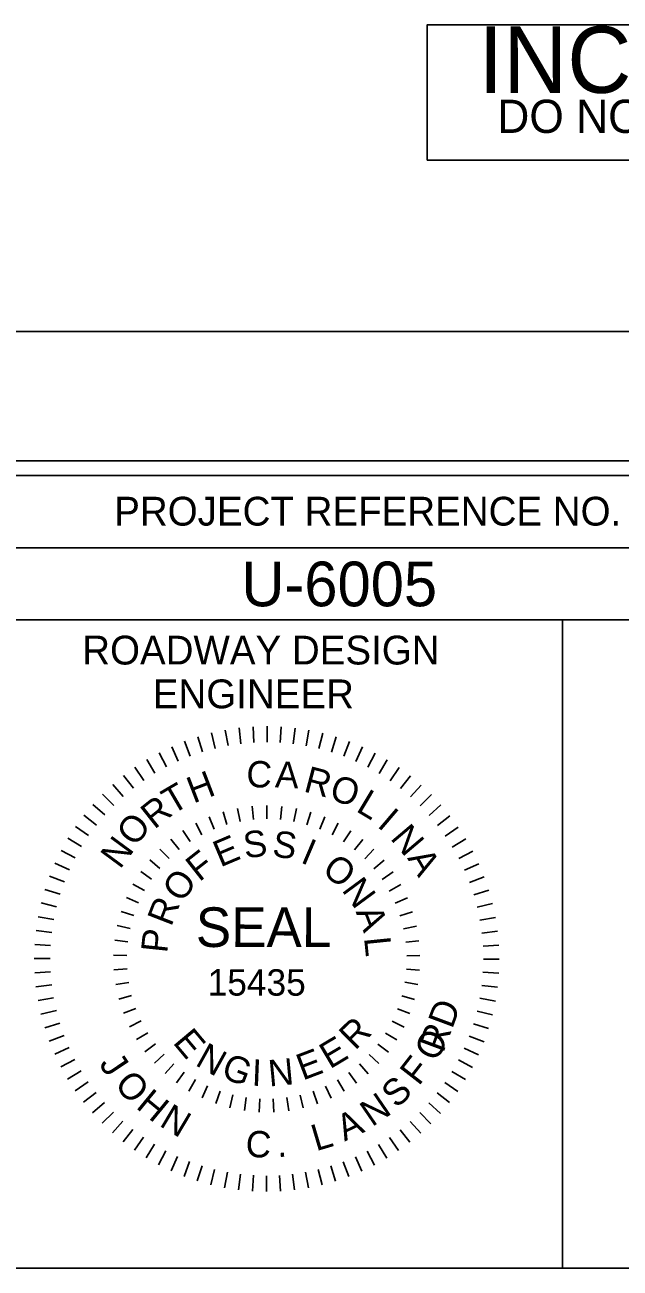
# Model space of a CAD drawing. Extents: x 1621288 to 1629363, y 896995 to 899414.
# Drawn here: x 1628776 to 1628879.4, y 897932.1 to 898147.8 of the extents above; entities that cross this region are included whole.
import ezdxf

# ---------------------------------------------------------------- set-up
doc = ezdxf.new("R2010")
doc.units = 0
for name, color, linetype in [('Exist Drainage Structure RD Basin Best Management Practices', 7, 'Continuous'), ('Exist XS Ground Line', 7, 'Continuous'), ('Prop Plan Preparation Cover Label', 7, 'Continuous'), ('Prop Vertical Profile Curve Label', 7, 'Continuous'), ('Prop Vertical Profile Grade Label', 7, 'Continuous'), ('Prop VPI Label', 7, 'Continuous'), ('Sheet Layout Plan Border', 7, 'Continuous'), ('Sheet Layout Profile Border', 7, 'Continuous')]:
    doc.layers.add(name, color=color, linetype=linetype)

msp = doc.modelspace()

# ---------------------------------------------------------------- linework, layer by layer
at = {"layer": 'Exist Drainage Structure RD Basin Best Management Practices'}
for p, q in [((1628815.65, 898026.08), (1628815.81, 898023.33)), ((1628818.09, 898026.15), (1628818.08, 898023.4)), ((1628820.52, 898026.07), (1628820.36, 898023.33)), ((1628806.07, 898024.34), (1628806.89, 898021.71)), ((1628808.43, 898024.99), (1628809.08, 898022.32)), ((1628810.81, 898025.5), (1628811.3, 898022.79)), ((1628813.22, 898025.86), (1628813.55, 898023.13)), ((1628822.95, 898025.85), (1628822.62, 898023.12)), ((1628825.36, 898025.48), (1628824.86, 898022.78)), ((1628827.74, 898024.97), (1628827.09, 898022.29)), ((1628830.1, 898024.31), (1628829.27, 898021.68)), ((1628801.52, 898022.61), (1628802.64, 898020.11)), ((1628803.77, 898023.55), (1628804.74, 898020.97)), ((1628832.4, 898023.51), (1628831.41, 898020.94)), ((1628834.65, 898022.57), (1628833.52, 898020.06)), ((1628797.19, 898020.36), (1628798.62, 898018)), ((1628799.32, 898021.55), (1628800.6, 898019.11)), ((1628836.84, 898021.5), (1628835.56, 898019.06)), ((1628838.96, 898020.3), (1628837.53, 898017.95)), ((1628793.18, 898017.59), (1628794.87, 898015.43)), ((1628795.14, 898019.04), (1628796.7, 898016.77)), ((1628841.01, 898018.97), (1628839.44, 898016.71)), ((1628842.97, 898017.53), (1628841.27, 898015.36)), ((1628791.3, 898016.03), (1628793.12, 898013.97)), ((1628844.84, 898015.96), (1628843.01, 898013.9)), ((1628789.53, 898014.37), (1628791.47, 898012.42)), ((1628846.61, 898014.29), (1628844.67, 898012.34)), ((1628787.85, 898012.59), (1628789.91, 898010.77)), ((1628810.46, 898011.29), (1628811.11, 898009.09)), ((1628812.96, 898011.9), (1628813.39, 898009.65)), ((1628815.5, 898012.27), (1628815.72, 898009.99)), ((1628818.07, 898012.39), (1628818.06, 898010.1)), ((1628818.06, 898010.1), (1628818.07, 898012.39)), ((1628820.64, 898012.26), (1628820.41, 898009.98)), ((1628823.18, 898011.89), (1628822.74, 898009.64)), ((1628825.67, 898011.27), (1628825.01, 898009.07)), ((1628848.28, 898012.51), (1628846.22, 898010.69)), ((1628784.84, 898008.76), (1628787.1, 898007.19)), ((1628786.29, 898010.72), (1628788.45, 898009.02)), ((1628805.7, 898009.36), (1628806.76, 898007.33)), ((1628808.03, 898010.44), (1628808.89, 898008.31)), ((1628828.1, 898010.41), (1628827.23, 898008.29)), ((1628830.43, 898009.32), (1628829.36, 898007.3)), ((1628849.84, 898010.63), (1628847.67, 898008.94)), ((1628783.51, 898006.72), (1628785.86, 898005.29)), ((1628801.4, 898006.55), (1628802.83, 898004.76)), ((1628803.48, 898008.06), (1628804.73, 898006.14)), ((1628832.64, 898008.02), (1628831.38, 898006.1)), ((1628851.28, 898008.67), (1628849.02, 898007.11)), ((1628852.6, 898006.62), (1628850.25, 898005.2)), ((1628782.31, 898004.59), (1628784.75, 898003.31)), ((1628799.47, 898004.85), (1628801.07, 898003.2)), ((1628834.72, 898006.5), (1628833.28, 898004.71)), ((1628836.64, 898004.8), (1628835.03, 898003.15)), ((1628853.8, 898004.49), (1628851.36, 898003.22)), ((1628781.24, 898002.4), (1628783.75, 898001.27)), ((1628797.72, 898002.97), (1628799.47, 898001.49)), ((1628838.39, 898002.91), (1628836.63, 898001.44)), ((1628854.86, 898002.3), (1628852.35, 898001.17)), ((1628780.3, 898000.15), (1628782.88, 897999.17)), ((1628796.15, 898000.93), (1628798.04, 897999.62)), ((1628839.95, 898000.87), (1628838.06, 897999.56)), ((1628794.8, 897998.75), (1628796.8, 897997.63)), ((1628841.3, 897998.68), (1628839.3, 897997.57)), ((1628855.8, 898000.04), (1628853.22, 897999.07)), ((1628779.5, 897997.85), (1628782.14, 897997.03)), ((1628793.65, 897996.44), (1628795.75, 897995.52)), ((1628842.44, 897996.37), (1628840.33, 897995.46)), ((1628856.59, 897997.74), (1628853.96, 897996.93)), ((1628778.85, 897995.5), (1628781.52, 897994.84)), ((1628792.74, 897994.04), (1628794.92, 897993.33)), ((1628843.34, 897993.97), (1628841.16, 897993.27)), ((1628857.24, 897995.39), (1628854.57, 897994.74)), ((1628778.33, 897993.11), (1628781.04, 897992.62)), ((1628792.06, 897991.56), (1628794.3, 897991.06)), ((1628844.02, 897991.49), (1628841.78, 897991)), ((1628857.75, 897993), (1628855.04, 897992.51)), ((1628777.97, 897990.7), (1628780.69, 897990.37)), ((1628858.11, 897990.59), (1628855.38, 897990.27)), ((1628777.74, 897988.28), (1628780.49, 897988.11)), ((1628791.62, 897989.03), (1628793.9, 897988.75)), ((1628844.45, 897988.95), (1628842.17, 897988.68)), ((1628858.33, 897988.17), (1628855.58, 897988)), ((1628777.66, 897985.84), (1628780.41, 897985.84)), ((1628791.43, 897986.46), (1628793.72, 897986.4)), ((1628844.63, 897986.39), (1628842.34, 897986.33)), ((1628858.4, 897985.73), (1628855.65, 897985.73)), ((1628777.73, 897983.4), (1628780.48, 897983.56)), ((1628791.49, 897983.89), (1628793.78, 897984.05)), ((1628844.56, 897983.82), (1628842.28, 897983.99)), ((1628858.32, 897983.29), (1628855.57, 897983.46)), ((1628777.95, 897980.97), (1628780.68, 897981.3)), ((1628791.8, 897981.34), (1628794.06, 897981.72)), ((1628842, 897981.74), (1628844.26, 897981.35)), ((1628858.09, 897980.86), (1628855.37, 897981.19)), ((1628778.31, 897978.56), (1628781.02, 897979.05)), ((1628792.35, 897978.83), (1628794.56, 897979.43)), ((1628843.69, 897978.76), (1628841.48, 897979.36)), ((1628857.73, 897978.45), (1628855.02, 897978.95)), ((1628778.82, 897976.18), (1628781.49, 897976.83)), ((1628793.14, 897976.38), (1628795.28, 897977.19)), ((1628842.89, 897976.31), (1628840.75, 897977.13)), ((1628857.21, 897976.07), (1628854.54, 897976.73)), ((1628779.47, 897973.82), (1628782.1, 897974.64)), ((1628794.17, 897974.03), (1628796.22, 897975.04)), ((1628841.86, 897973.96), (1628839.81, 897974.98)), ((1628856.55, 897973.72), (1628853.92, 897974.54)), ((1628780.26, 897971.52), (1628782.84, 897972.5)), ((1628795.41, 897971.78), (1628797.36, 897972.98)), ((1628840.61, 897971.72), (1628838.66, 897972.92)), ((1628855.76, 897971.42), (1628853.18, 897972.4)), ((1628781.2, 897969.27), (1628783.71, 897970.39)), ((1628796.87, 897969.66), (1628798.69, 897971.05)), ((1628839.15, 897969.6), (1628837.33, 897970.99)), ((1628854.81, 897969.17), (1628852.31, 897970.3)), ((1628782.26, 897967.07), (1628784.7, 897968.35)), ((1628798.52, 897967.69), (1628800.2, 897969.25)), ((1628837.49, 897967.64), (1628835.81, 897969.2)), ((1628853.75, 897966.97), (1628851.31, 897968.26)), ((1628783.45, 897964.95), (1628785.81, 897966.37)), ((1628800.36, 897965.89), (1628801.88, 897967.61)), ((1628802.36, 897964.28), (1628803.71, 897966.13)), ((1628833.64, 897964.24), (1628832.29, 897966.09)), ((1628835.65, 897965.85), (1628834.13, 897967.56)), ((1628852.55, 897964.85), (1628850.19, 897966.28)), ((1628784.78, 897962.9), (1628787.04, 897964.46)), ((1628804.51, 897962.87), (1628805.68, 897964.85)), ((1628806.79, 897961.67), (1628807.76, 897963.75)), ((1628829.21, 897961.64), (1628828.24, 897963.72)), ((1628831.49, 897962.83), (1628830.32, 897964.81)), ((1628851.22, 897962.8), (1628848.96, 897964.37)), ((1628786.22, 897960.93), (1628788.39, 897962.63)), ((1628809.17, 897960.7), (1628809.93, 897962.86)), ((1628812.16, 897962.19), (1628811.61, 897959.96)), ((1628814.15, 897959.46), (1628814.48, 897961.73)), ((1628816.71, 897959.21), (1628816.82, 897961.5)), ((1628819.28, 897959.21), (1628819.17, 897961.5)), ((1628821.84, 897959.45), (1628821.51, 897961.72)), ((1628824.36, 897959.94), (1628823.81, 897962.17)), ((1628826.82, 897960.67), (1628826.06, 897962.84)), ((1628849.77, 897960.85), (1628847.61, 897962.54)), ((1628787.78, 897959.06), (1628789.84, 897960.88)), ((1628789.45, 897957.28), (1628791.39, 897959.22)), ((1628846.53, 897957.2), (1628844.59, 897959.15)), ((1628848.21, 897958.97), (1628846.15, 897960.8)), ((1628791.22, 897955.61), (1628793.05, 897957.66)), ((1628844.76, 897955.53), (1628842.93, 897957.59)), ((1628793.09, 897954.04), (1628794.79, 897956.2)), ((1628795.05, 897952.59), (1628796.62, 897954.85)), ((1628840.92, 897952.53), (1628839.36, 897954.79)), ((1628842.88, 897953.97), (1628841.19, 897956.14)), ((1628797.1, 897951.27), (1628798.53, 897953.62)), ((1628838.87, 897951.21), (1628837.44, 897953.56)), ((1628799.22, 897950.06), (1628800.5, 897952.5)), ((1628801.41, 897949), (1628802.54, 897951.5)), ((1628803.66, 897948.06), (1628804.64, 897950.63)), ((1628832.29, 897948.02), (1628831.32, 897950.59)), ((1628834.54, 897948.95), (1628833.42, 897951.46)), ((1628836.74, 897950.01), (1628835.46, 897952.45)), ((1628805.96, 897947.26), (1628806.79, 897949.89)), ((1628808.32, 897946.6), (1628808.97, 897949.27)), ((1628810.7, 897946.09), (1628811.2, 897948.79)), ((1628813.11, 897945.72), (1628813.44, 897948.45)), ((1628822.84, 897945.71), (1628822.51, 897948.43)), ((1628825.25, 897946.07), (1628824.76, 897948.77)), ((1628827.63, 897946.57), (1628826.98, 897949.25)), ((1628829.99, 897947.22), (1628829.17, 897949.86)), ((1628815.53, 897945.49), (1628815.7, 897948.24)), ((1628817.97, 897945.42), (1628817.98, 897948.17)), ((1628820.41, 897945.49), (1628820.25, 897948.23))]:
    msp.add_line(p, q, dxfattribs=at)
at = {"layer": 'Exist XS Ground Line'}
for p, q in [((1628769.33, 898057.11), (1628969.38, 898057.11)), ((1628869.38, 898044.61), (1628869.38, 897932.16))]:
    msp.add_line(p, q, dxfattribs=at)
for points in [[(1628969.38, 898069.66), (1627469.38, 898069.66), (1627469.38, 897019.66), (1628969.38, 897019.66)], [(1628769.33, 898069.66), (1628969.38, 898069.66), (1628969.38, 898044.61), (1628769.33, 898044.61)], [(1628769.33, 898044.61), (1628869.38, 898044.61), (1628869.38, 897932.11), (1628769.33, 897932.11)], [(1628869.38, 898044.61), (1628969.38, 898044.61), (1628969.38, 897932.11), (1628869.38, 897932.11)]]:
    msp.add_lwpolyline(points, close=True, dxfattribs=at)
at = {"layer": 'Prop Plan Preparation Cover Label'}
msp.add_lwpolyline([(1628845.86, 898124.35), (1628845.86, 898147.85), (1628992.86, 898147.85), (1628992.86, 898124.35)], close=True, dxfattribs=at)
at = {"layer": 'Prop Vertical Profile Curve Label'}
msp.add_lwpolyline([(1627315.38, 897017.11), (1628981.88, 897017.11), (1628981.88, 898072.21), (1627315.38, 898072.21)], close=True, dxfattribs=at)
at = {"layer": 'Prop VPI Label'}
msp.add_lwpolyline([(1628269.38, 898069.66), (1628319.38, 898069.66), (1628319.38, 897569.66), (1628369.38, 897569.66), (1628369.38, 898069.66), (1628419.38, 898069.66), (1628419.38, 897569.66), (1628469.38, 897569.66), (1628469.38, 898069.66), (1628519.38, 898069.66), (1628519.38, 897569.66), (1628569.38, 897569.66), (1628569.38, 898069.66), (1628619.38, 898069.66), (1628619.38, 897569.66), (1628669.38, 897569.66), (1628669.38, 898069.66), (1628719.38, 898069.66), (1628719.38, 897569.66), (1628769.38, 897569.66), (1628769.38, 898069.66), (1628795.68, 898069.66)], dxfattribs=at)
at = {"layer": 'Sheet Layout Plan Border'}
msp.add_lwpolyline([(1627302.38, 896994.66), (1628986.38, 896994.66), (1628986.38, 898094.66), (1627302.38, 898094.66)], close=True, dxfattribs=at)
at = {"layer": 'Sheet Layout Profile Border'}
msp.add_line((1628986.38, 898094.66), (1627302.38, 898094.66), dxfattribs=at)

# ---------------------------------------------------------------- texts
at = {"layer": 'Exist Drainage Structure RD Basin Best Management Practices'}
for s, height, rotation, p in [('C', 4.58, 357.2771, (1628814.4, 898015.65)), ('A', 4.58, 357.2771, (1628819.41, 898015.55)), ('H', 4.58, 20.9878, (1628805.28, 898012.72)), ('R', 4.58, 345.2678, (1628824.27, 898014.87)), ('O', 4.58, 342.211, (1628828.7, 898013.54)), ('T', 4.58, 30.4198, (1628801.59, 898010.73)), ('R', 4.58, 38.5807, (1628798.51, 898008.17)), ('L', 4.58, 329.0747, (1628833.36, 898011.5)), ('I', 4.58, 319.4993, (1628837.05, 898008.83)), ('O', 4.58, 51.6375, (1628795.18, 898005.09)), ('N', 4.58, 310.2048, (1628839.35, 898006.67)), ('N', 4.58, 53.5969, (1628792.54, 898001.22)), ('E', 4.58, 22.8645, (1628809.97, 898001.64)), ('S', 4.58, 7.5683, (1628814.27, 898003.21)), ('S', 4.58, 352.272, (1628818.85, 898003.59)), ('I', 4.58, 336.9758, (1628823.72, 898002.59)), ('F', 4.58, 38.1608, (1628806.3, 897999.06)), ('O', 4.58, 321.6795, (1628827.41, 898000.8)), ('A', 4.58, 300.4373, (1628842.37, 898003.28)), ('O', 4.58, 53.457, (1628803.25, 897995.37)), ('N', 4.58, 306.3833, (1628830.94, 897997.73)), ('R', 4.58, 68.7533, (1628801.43, 897991.25)), ('SEAL', 6.878, 359.9202, (1628805.71, 897987.86)), ('A', 4.58, 291.0871, (1628833.45, 897993.97)), ('P', 4.58, 84.0495, (1628800.73, 897986.71)), ('L', 4.58, 275.7908, (1628834.92, 897989.43)), ('15435', 4.582, 359.9202, (1628807.76, 897979.43)), (' RD', 4.582, 69.5926, (1628848.08, 897967.77)), ('R', 4.58, 44.4851, (1628833.36, 897969.79)), ('E', 4.58, 309.9903, (1628801.59, 897971.25)), ('E', 4.58, 30.714, (1628828.99, 897966.6)), ('O ', 4.582, 60.9198, (1628847.41, 897967.75)), ('N', 4.58, 330.8453, (1628805.43, 897967.43)), ('E', 4.58, 20.7281, (1628824.28, 897964.66)), ('J', 4.58, 303.8552, (1628788.8, 897967.53)), ('G', 4.58, 339.6116, (1628809.91, 897965.27)), ('I', 4.58, 357.7064, (1628815.37, 897963.8)), ('N', 4.58, 5.336, (1628818.48, 897963.64)), ('F', 4.58, 52.1272, (1628844.42, 897963.62)), ('O', 4.58, 311.927, (1628791.41, 897963.87)), ('S', 4.58, 43.2446, (1628840.6, 897959.73)), ('H', 4.58, 320.5697, (1628795.15, 897960.01)), ('N', 4.58, 34.362, (1628836.31, 897956.56)), ('N', 4.58, 329.2423, (1628799.2, 897956.91)), ('A', 4.58, 25.5393, (1628831.54, 897954.07)), ('L', 4.58, 16.5368, (1628826.59, 897952.4)), ('C', 4.58, 356.0101, (1628814.23, 897951.52)), ('.', 4.58, 3.7525, (1628819.92, 897951.39))]:
    msp.add_text(s, height=height, rotation=rotation, dxfattribs=at).set_placement(p)
at = {"layer": 'Exist XS Ground Line'}
for s, height, p in [('PROJECT REFERENCE NO.', 5.0001, (1628791.54, 898060.97)), ('ROADWAY DESIGN', 5.0001, (1628785.99, 898036.87)), ('ENGINEER', 5, (1628798.24, 898029.27))]:
    msp.add_text(s, height=height, dxfattribs=at).set_placement(p)
at = {"layer": 'Prop Plan Preparation Cover Label'}
for s, height, p in [('INCOMPLETE PLANS', 11.52, (1628854.81, 898136.05)), ('DO NOT USE FOR R/W ACQUISITION', 5.76, (1628858.06, 898129.1))]:
    msp.add_text(s, height=height, dxfattribs=at).set_placement(p)
at = {"layer": 'Prop Vertical Profile Grade Label'}
msp.add_text('U-6005', height=7.75, dxfattribs=at).set_placement((1628813.62, 898046.97))

doc.saveas('drawing.dxf')
